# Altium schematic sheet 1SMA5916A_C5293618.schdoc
size 127 x 101 mm
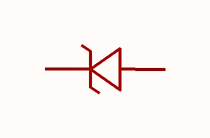
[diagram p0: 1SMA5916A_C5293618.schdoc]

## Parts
D?  1sma5916a_c5293618  [SMA_L4.4-W2.6-LS5.1-RD]  (value not drawn)

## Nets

Not connected (* = marked no-connect by the designer): D? 1(C) 2(A)

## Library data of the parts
D? = 1sma5916a_c5293618: 二极管配置:1个独立式;稳压值(标称值):4.3V;稳压值(范围值):4.08V~4.52V;耗散功率(Pd):1.5W;; Manufacturer: CJ(江苏长电/长晶); AddInBom: yes; ModelId: 21b4297b05f34eb58397f8f5cb4541ec; ModelTransform: 200.787,102.362,0,0,0,0,0,0,0; Diode Configuration: 1个独立式; Zener Voltage(Nom): 4.3V; Reverse Leakage Current (Ir): 2.5uA@1V; Pd - Power Dissipation: 1.5W; Impedance(Zzt): 6Ω; Impedance(Zzk): 500Ω; Operating Junction Temperature Range: -55℃~+150℃; Tolerance: ±5%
